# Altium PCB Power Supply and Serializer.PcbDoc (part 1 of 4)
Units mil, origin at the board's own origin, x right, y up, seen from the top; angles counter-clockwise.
Board outline 986 x 985 mil, 8 copper layers (TOP, GND1, INNER1, GND2, PWR1, INNER2, GND3, BOTTOM), stack 60.4 mil thick; 91 components, 64 nets, 288 pads, 200 vias.
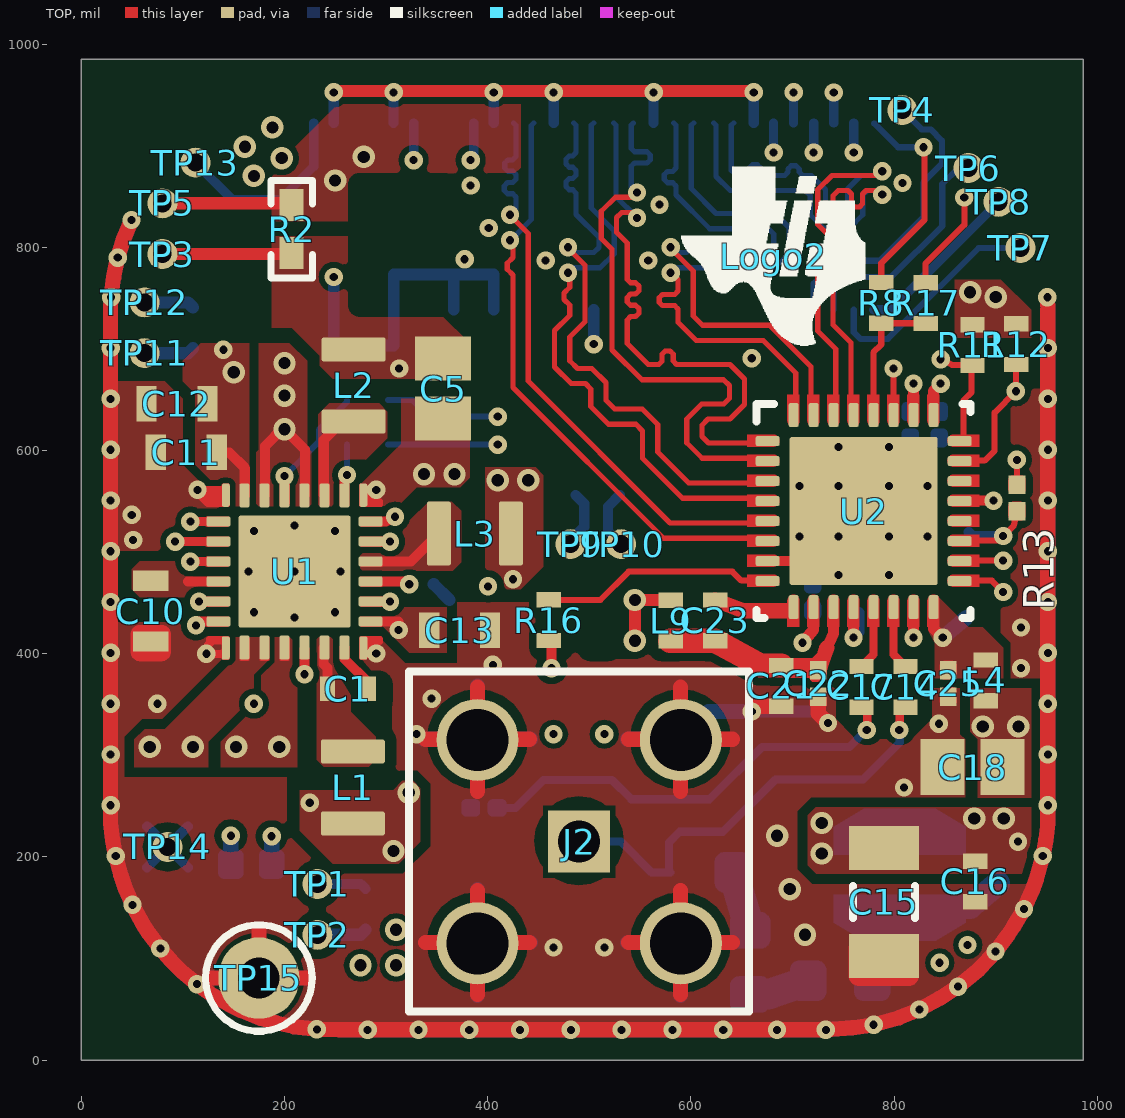
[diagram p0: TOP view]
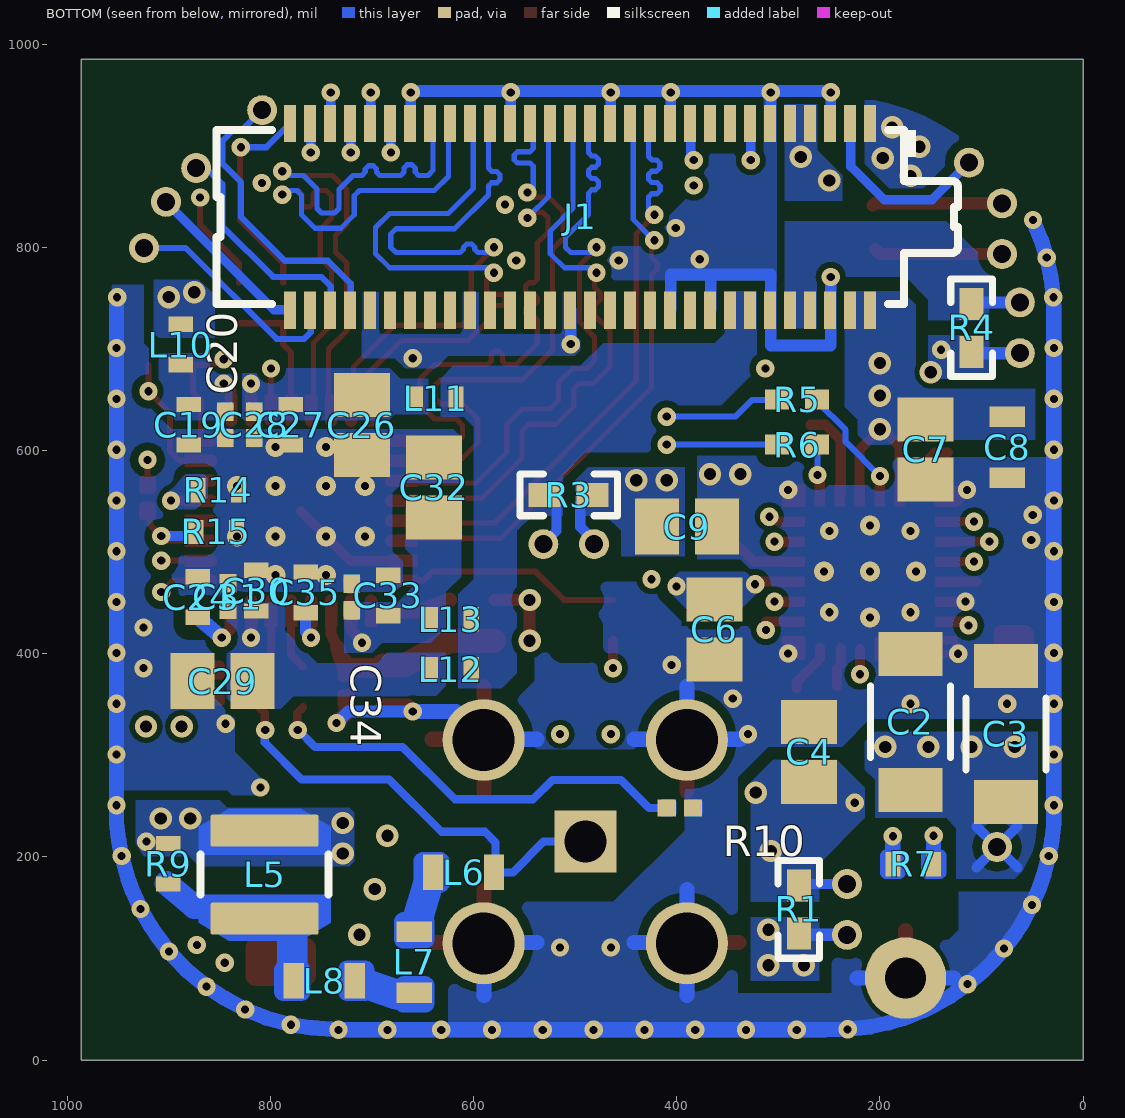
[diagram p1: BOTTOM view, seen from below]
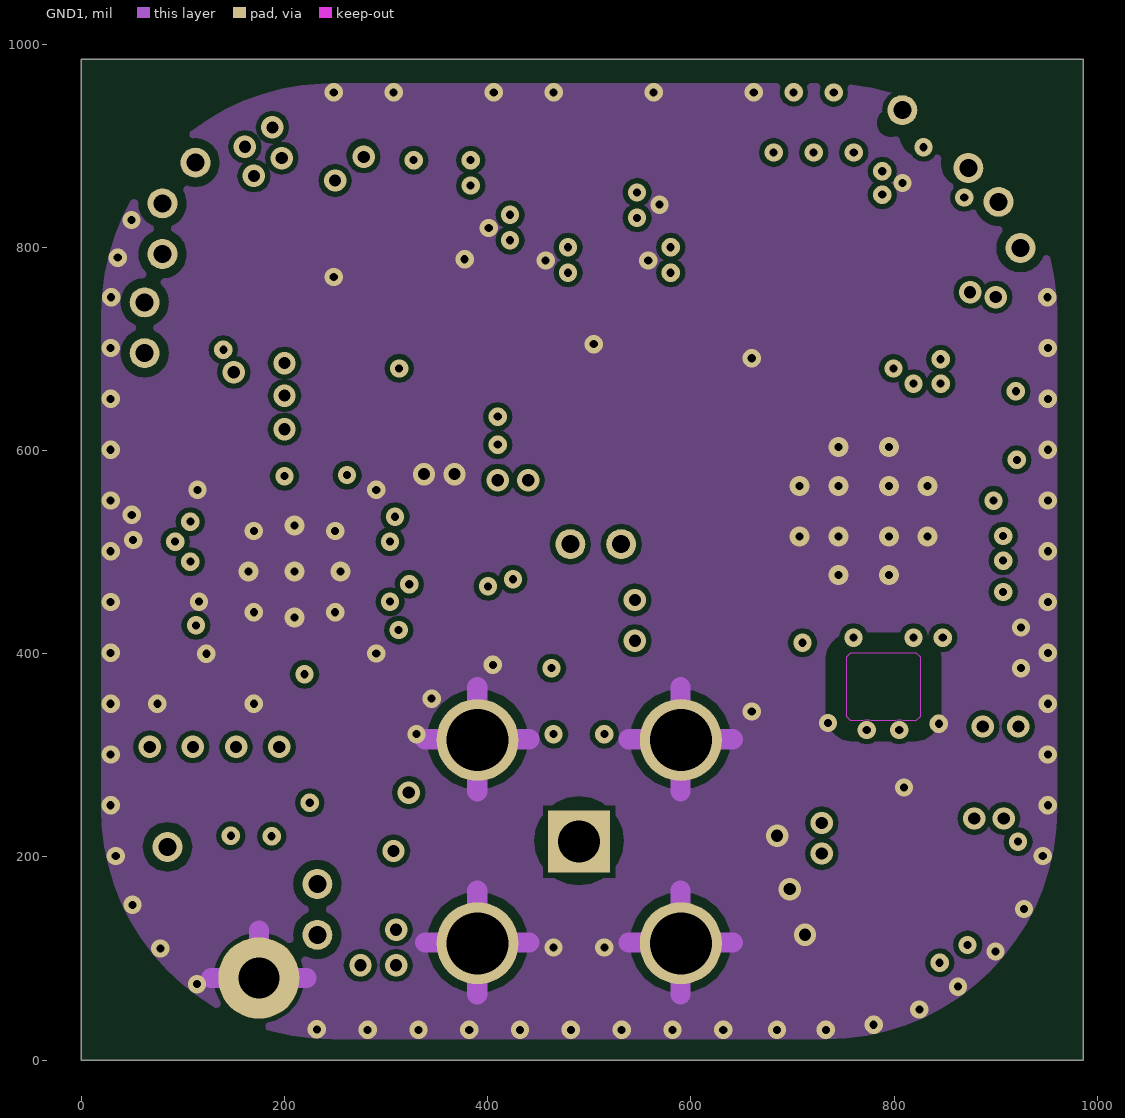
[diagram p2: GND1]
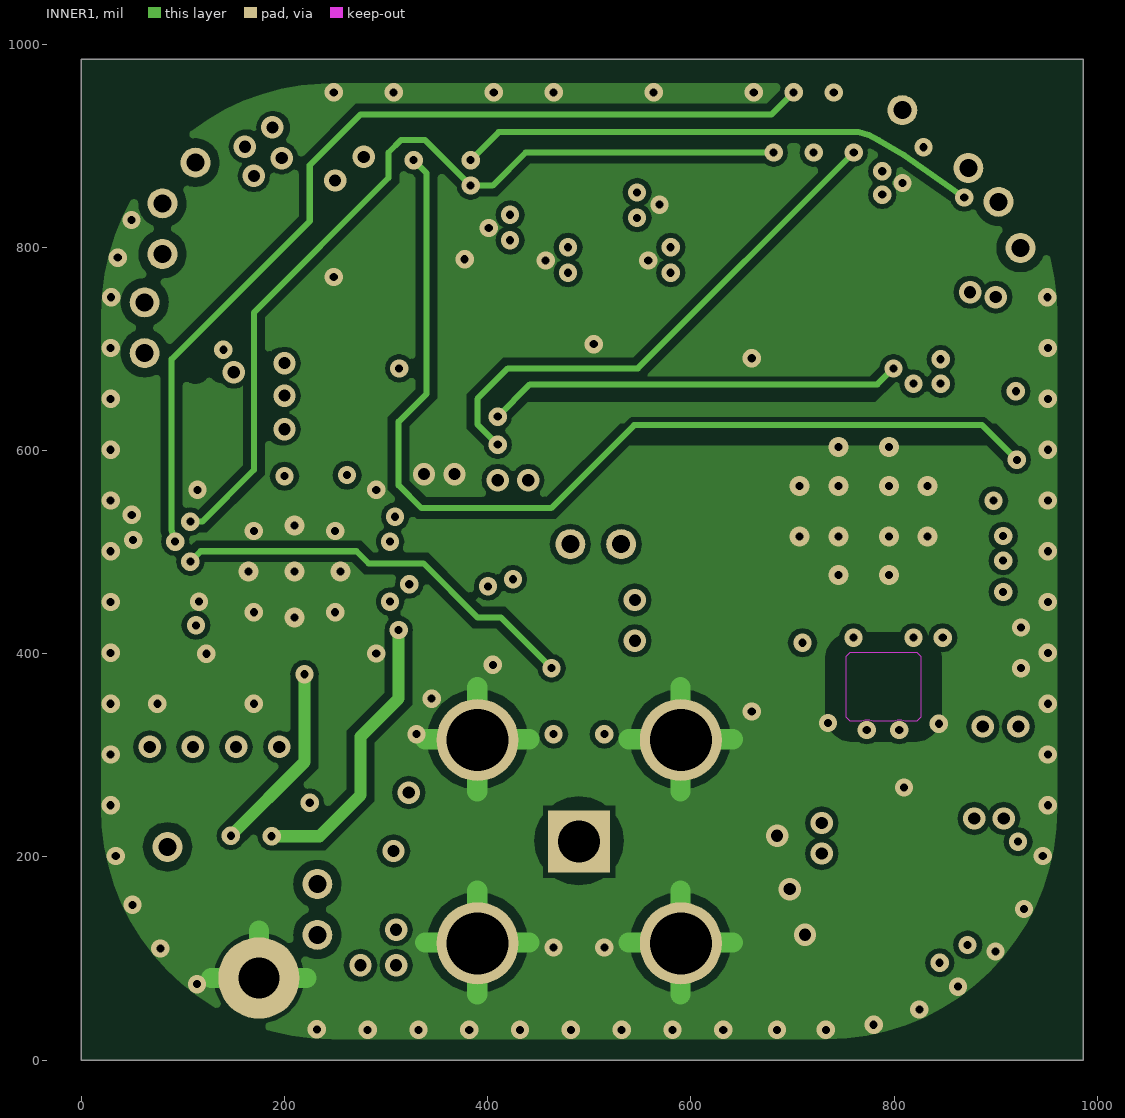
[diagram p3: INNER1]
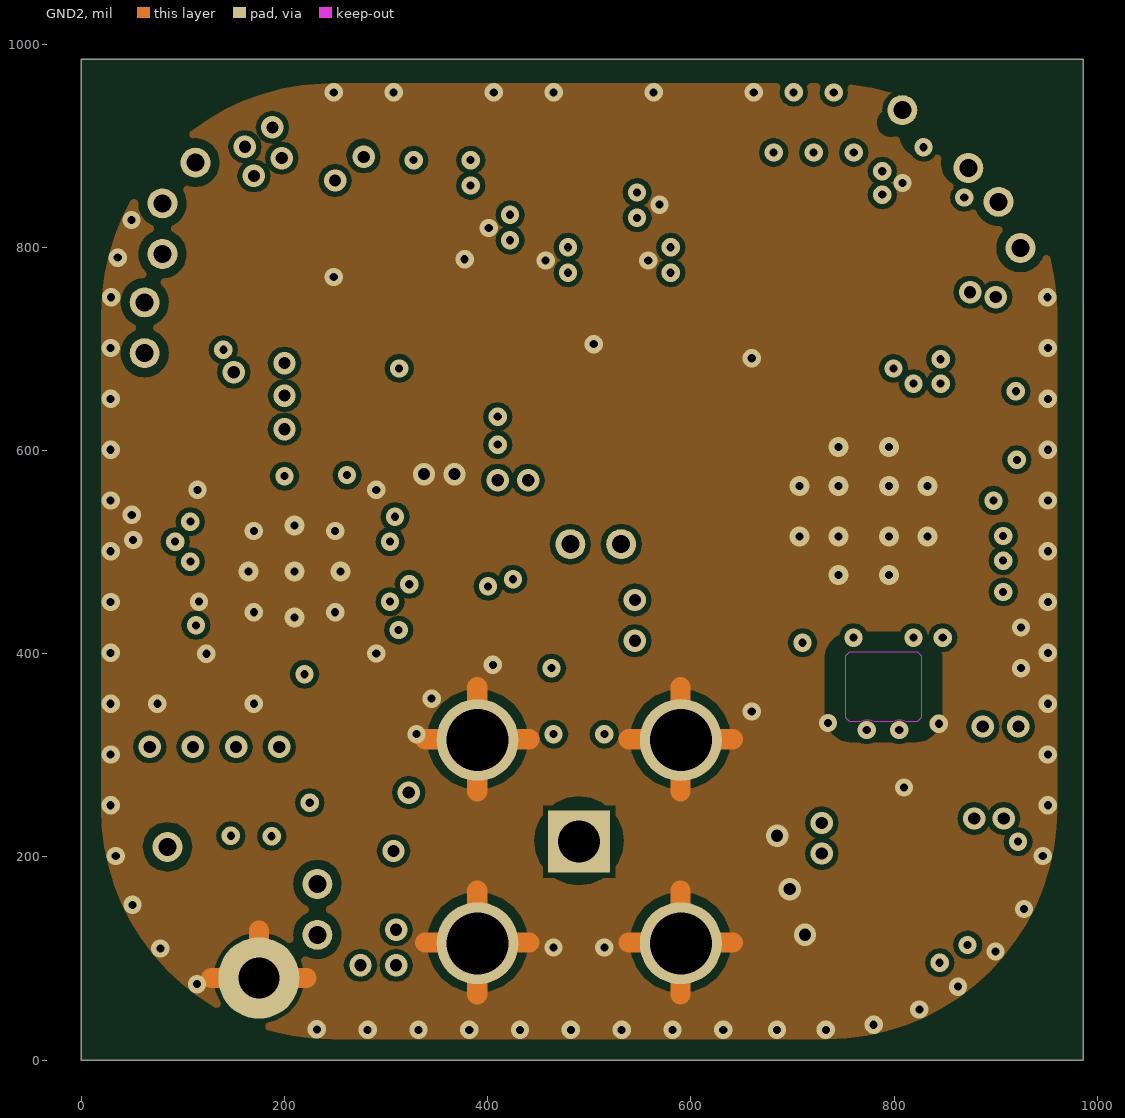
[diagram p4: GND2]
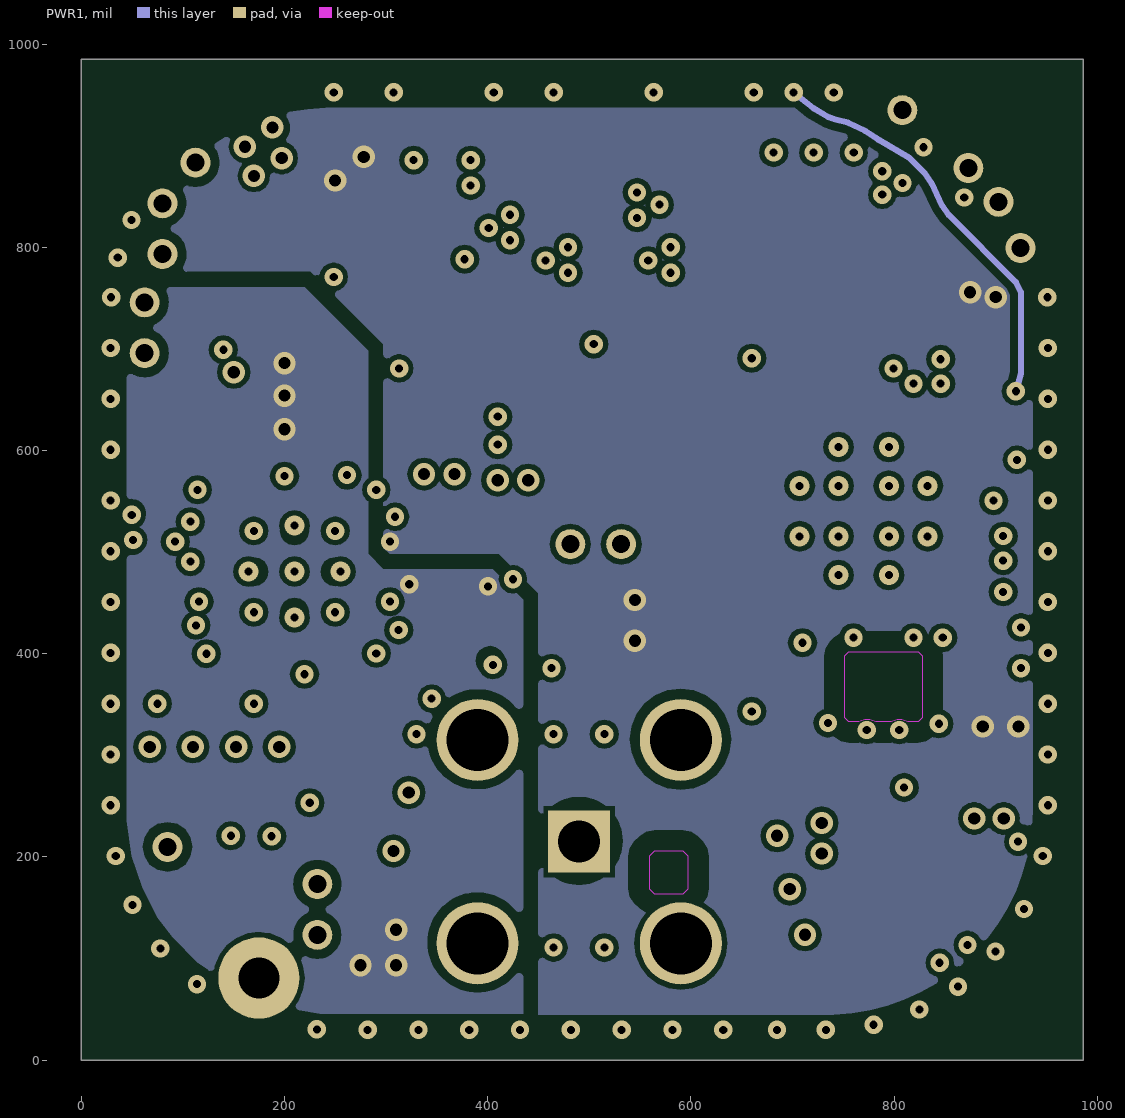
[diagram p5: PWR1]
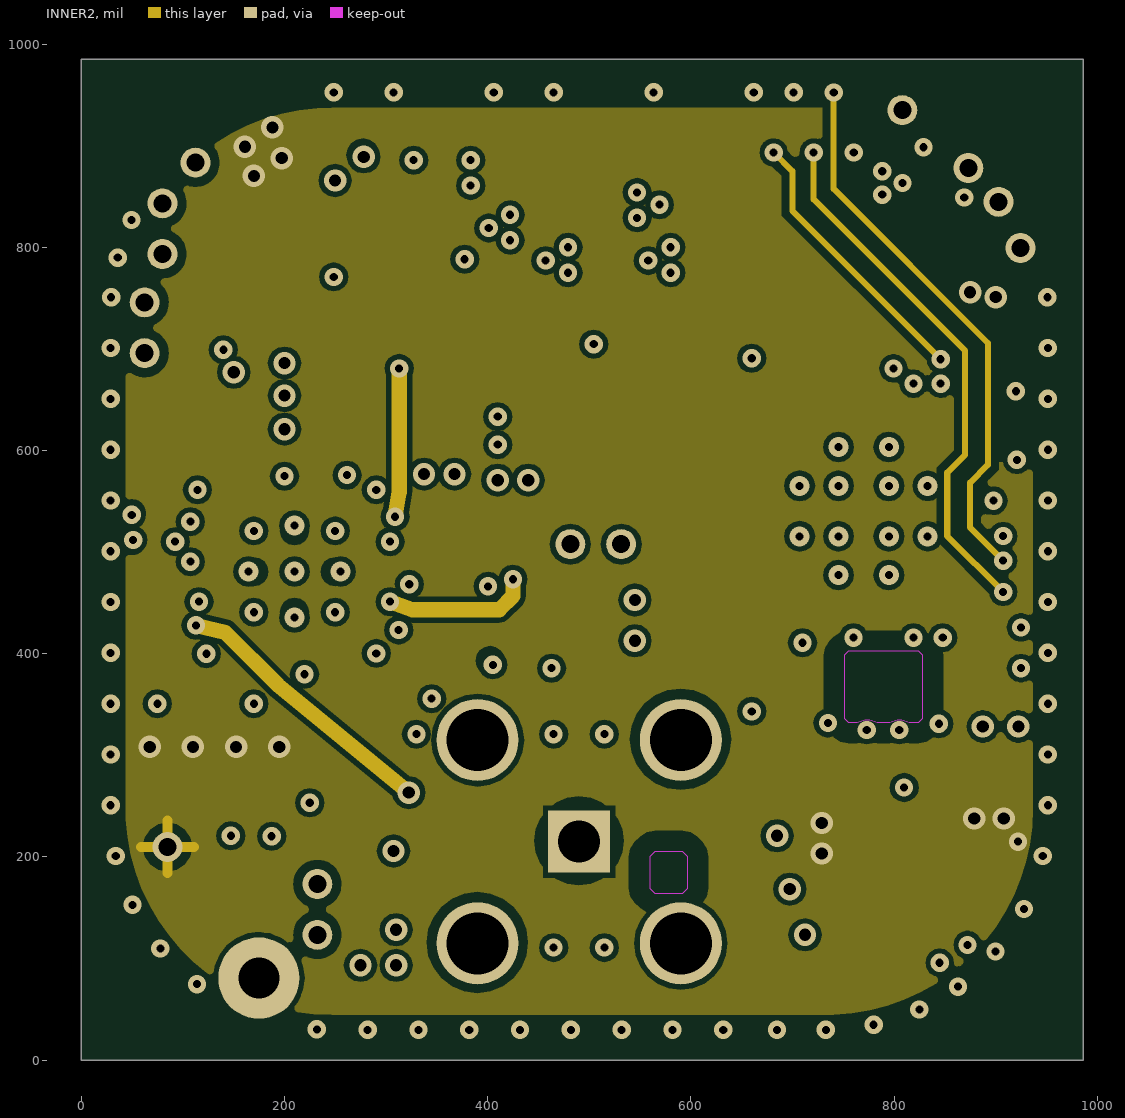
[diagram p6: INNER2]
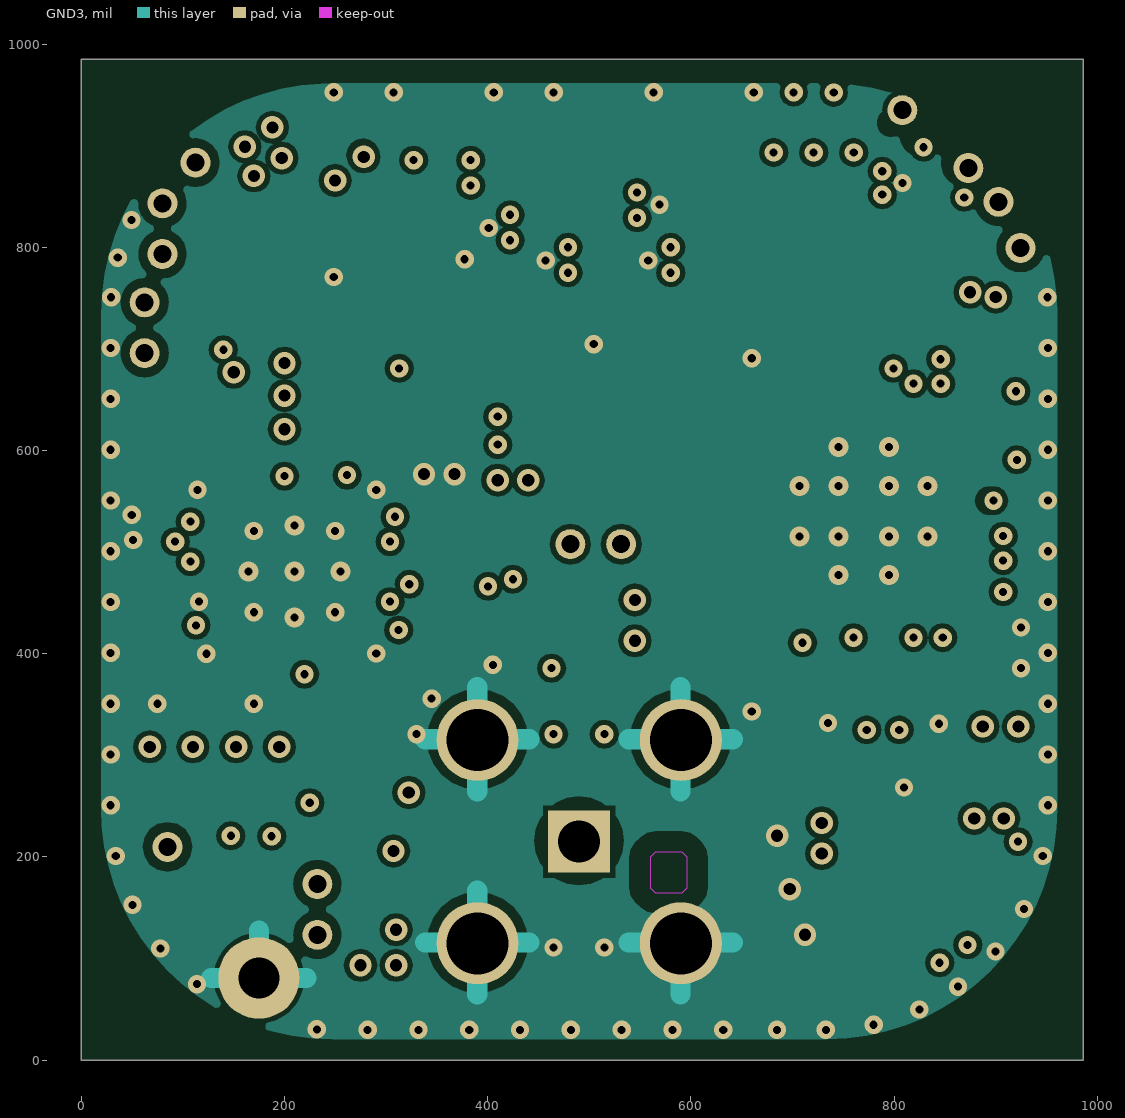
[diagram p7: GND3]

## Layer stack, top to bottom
Top Solder: solder mask 0.4, Solder Resist, Dk 3.5
TOP: signal copper 2.1
Dielectric 1: core 3.2, FR-4, Dk 3.8
GND1: signal copper 1.3
Dielectric2: core 5, FR-4, Dk 3.8
INNER1: signal copper 1.3
Dielectric3: core 9, FR-4, Dk 3.8
GND2: signal copper 1.3
Dielectric4: core 14, FR-4, Dk 3.8
PWR1: signal copper 1.3
Dielectric5: core 9, FR-4, Dk 3.8
INNER2: signal copper 1.3
Dielectric6: core 5, FR-4, Dk 3.8
GND3: signal copper 1.3
Dielectric7: core 3.2, FR-4, Dk 3.8
BOTTOM: signal copper 2.1
Bottom Solder: solder mask 0.4, Solder Resist, Dk 3.5

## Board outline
0,0 0,985 986,985 986,0

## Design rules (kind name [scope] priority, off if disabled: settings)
AcuteAngle [All] p1 off: minimum=4.50000000000000E+0001 checktracksonly=FALSE
AssemblyTestPointUsage [All] p1: valid=2
Clearance Clearance_BoardEdge_MountingHoles [OnCopper and InComponentClass('Mounting Holes') vs IsKeepOut] p1 off: gap=30 ignorepadtopadclearanceinfootprint=FALSE except(0: Arc-Hole Track-Hole SMDPad-Hole THPad-Hole Via-Hole Fill-Hole Poly-Hole Region-Hole Text-Hole)
Clearance Clearance_BoardEdge_Poly [OnCopper and InPoly vs IsKeepOut] p2: gap=20 ignorepadtopadclearanceinfootprint=FALSE except(0: Arc-Hole Track-Hole SMDPad-Hole THPad-Hole Via-Hole Fill-Hole Poly-Hole Region-Hole Text-Hole)
Clearance Clearance_BoardEdge [OnCopper and Not InComponentClass('Logo') and not InComponentClass('FiducialMark') and not InRegion(1000,500,4000,800) and Not IsKeepout vs IsKeepOut and Not OnLayer('Keep-out Layer')] p3: gap=11 ignorepadtopadclearanceinfootprint=FALSE except(0: Arc-Hole Track-Hole SMDPad-Hole THPad-Hole Via-Hole Fill-Hole Poly-Hole Region-Hole Text-Hole)
Clearance Clearance_Poly [InPolygon] p4: gap=10 ignorepadtopadclearanceinfootprint=FALSE except(0: Arc-Hole Track-Hole SMDPad-Hole THPad-Hole Via-Hole Fill-Hole Poly-Hole Region-Hole Text-Hole; 5: Arc-Fill Arc-Poly Arc-Region Track-Fill Track-Poly Track-Region SMDPad-Fill SMDPad-Poly SMDPad-Region THPad-Fill THPad-Poly THPad-Region Via-Fill Via-Poly Via-Region Fill-Fill Fill-Poly Fill-Region Poly-Poly Poly-Region Region-Region)
Clearance [All] p5: gap=5 ignorepadtopadclearanceinfootprint=FALSE except(0: Arc-Hole Track-Hole SMDPad-Hole THPad-Hole Via-Hole Fill-Hole Poly-Hole Region-Hole Text-Hole)
ComponentClearance ComponentClearance_1 [issmtcomponent] p1: gap=5 collisioncheckmode=3 verticalgap=0 showdistances=FALSE
ComponentClearance ComponentClearance_Shunt [InComponentClass('Header') vs InComponentClass('Shunt')] p2: gap=0 collisioncheckmode=3 verticalgap=0 showdistances=FALSE
ComponentClearance ComponentClearance_Logo [InComponentClass('Logo')] p3: gap=0 collisioncheckmode=3 verticalgap=0 showdistances=FALSE
ComponentClearance ComponentClearance_ScrewToNut [(HasFootprint('NY PMS 440 0025 PH')) vs (HasFootprint('Keystone_1902C'))] p4: gap=5 collisioncheckmode=3 verticalgap=10 showdistances=FALSE
ComponentClearance ComponentClearance_MountingHoles [InComponentClass('Mounting Holes')] p5: gap=50 collisioncheckmode=3 verticalgap=50 showdistances=FALSE
ComponentClearance ComponentClearance_SmallPassives [HasFootprint('0201*') or HasFootprint('0402*') or HasFootprint('0508') or HasFootprint('0603*') or HasFootprint('0612') or HasFootprint('0805*') or HasFootprint('0815*') or HasFootprint('0830*') or HasFootprint('1206*') or HasFootprint('1210*') or HasFootprint('1808*') or HasFootprint('1812*') or HasFootprint('1825*') or HasFootprint('2010*') or HasFootprint('2220*') or HasFootprint('2225*') or HasFootprint('2512*') or HasFootprint('2728*') or HasFootprint('3518*') vs HasFootprint('0201*') or HasFootprint('0402*') or HasFootprint('0508') or HasFootprint('0603*') or HasFootprint('0612') or HasFootprint('0805*') or HasFootprint('0815*') or HasFootprint('0830*') or HasFootprint('1206*') or HasFootprint('1210*') or HasFootprint('1808*') or HasFootprint('1812*') or HasFootprint('1825*') or HasFootprint('2010*') or HasFootprint('2220*') or HasFootprint('2225*') or HasFootprint('2512*') or HasFootprint('2728*') or HasFootprint('3518*')] p6: gap=5 collisioncheckmode=3 verticalgap=0 showdistances=FALSE
ComponentClearance ComponentClearance_THtoSMT [IsThruComponent vs IsSMTComponent] p7: gap=0 collisioncheckmode=3 verticalgap=0 showdistances=FALSE
ComponentClearance ComponentClearance_THtoTH [IsThruComponent vs IsThruComponent] p8: gap=0 collisioncheckmode=3 verticalgap=0 showdistances=FALSE
ComponentClearance [All] p9: gap=5 collisioncheckmode=3 verticalgap=0 showdistances=FALSE
DiffPairsRouting DiffPair_Diff100_DiffPairsRouting [InDifferentialPairClass('Diff100')] p1: maxlimit=8 minlimit=5 mostfreqgap=8 toplayer_mingap=8 toplayer_minwidth=8 toplayer_maxwidth=8 toplayer_prefwidth=8 midlayer1_mingap=8 midlayer1_minwidth=8 midlayer1_maxwidth=8 midlayer1_prefwidth=8 midlayer2_mingap=8 midlayer2_minwidth=8 midlayer2_maxwidth=8 midlayer2_prefwidth=8 midlayer3_maxgap=5 midlayer3_prefgap=5 midlayer3_minwidth=5 midlayer3_maxwidth=5 midlayer3_prefwidth=5 midlayer4_maxgap=5 midlayer4_prefgap=5 midlayer4_minwidth=5 midlayer4_maxwidth=5 midlayer4_prefwidth=5 midlayer5_mingap=8 midlayer5_minwidth=8 midlayer5_maxwidth=8 midlayer5_prefwidth=8 midlayer6_mingap=8 midlayer6_minwidth=8 midlayer6_maxwidth=8 midlayer6_prefwidth=8 bottomlayer_mingap=8 bottomlayer_minwidth=8 bottomlayer_maxwidth=8 bottomlayer_prefwidth=8 maxuncoupledlength=500
DiffPairsRouting [All] p2: maxlimit=100 minlimit=5 mostfreqgap=5 toplayer_maxgap=5 toplayer_minwidth=4 toplayer_maxwidth=15 toplayer_prefwidth=4 midlayer1_maxgap=5 midlayer1_minwidth=4 midlayer1_maxwidth=15 midlayer1_prefwidth=4 midlayer2_maxgap=5 midlayer2_minwidth=4 midlayer2_maxwidth=15 midlayer2_prefwidth=4 midlayer3_maxgap=5 midlayer3_minwidth=4 midlayer3_maxwidth=15 midlayer3_prefwidth=4 midlayer4_maxgap=5 midlayer4_minwidth=4 midlayer4_maxwidth=15 midlayer4_prefwidth=4 midlayer5_minwidth=4 midlayer5_maxwidth=15 midlayer5_prefwidth=4 midlayer6_minwidth=4 midlayer6_maxwidth=15 midlayer6_prefwidth=4 bottomlayer_maxgap=5 bottomlayer_minwidth=4 bottomlayer_maxwidth=15 bottomlayer_prefwidth=4 maxuncoupledlength=1000
FabricationTestPointUsage TestPointUsage [All] p1: valid=2 allowmultiple=FALSE
FabricationTestpoint Testpoint [All] p1: side=3 testpointundercomponent=TRUE minsize=40 maxsize=100 preferedsize=60 minholesize=0 maxholesize=40 preferedholesize=32 testpointgrid=1 allowsidetop=TRUE allowsidebottom=TRUE usegrid=TRUE gridtolerance=0.01
FanoutControl Fanout_LCC [IsLCC] p1: bgadir=Out bgaviamode=Centered fanoutstyle=Auto fanoutdirection=Alternating viagrid=1 // Fanout_LCC (Default Rule)
FanoutControl Fanout_BGA [IsBGA] p2: bgadir=Out bgaviamode=Centered fanoutstyle=Auto fanoutdirection=Alternating viagrid=1 // Fanout_BGA (Default Rule)
FanoutControl Fanout_Default [All] p4: bgadir=Out bgaviamode=Centered fanoutstyle=Auto fanoutdirection=Alternating viagrid=1 // Fanout_Default (Default Rule)
FanoutControl Fanout_Small [(CompPinCount < 5)] p5: bgadir=Out bgaviamode=Centered fanoutstyle=Auto fanoutdirection=OutThenIn viagrid=1 // Fanout_Small (Default Rule)
HoleSize [All] p1: absolutevalues=TRUE maxlimit=280 minlimit=6 maxpercent=80.000 minpercent=20.000
MatchedLengths DiffPair_Diff100_MatchedLengths [InDifferentialPairClass('Diff100')] p1: tolerance=25 checknetsindiffpair=FALSE checkdiffpairvsdiffpair=TRUE checkxsignals=TRUE checkothers=TRUE
MinimumAnnularRing MinimumAnnularRing_ThermalPadVias [IsVia and InAnyComponent] p1: minimumring=5.91
MinimumAnnularRing [All] p2: minimumring=2
MinimumSolderMaskSliver MinimumSolderMaskSliver_Logo [InComponentClass('Logo') vs InComponentClass('Logo')] p1: minsoldermaskwidth=0.7
MinimumSolderMaskSliver [All] p2: minsoldermaskwidth=1
PlaneConnect [All] p1: planeconnectstyle=Relief reliefexpansion=10 reliefentries=4 reliefconductorwidth=10 reliefairgap=10
PolygonConnect [All] p1: connectstyle=Direct reliefconductorwidth=10 reliefentries=4 polygonreliefangle="90 Angle" airgapwidth=10
RoutingVias ThermalPadVias [IsVia and InAnyComponent] p1: holewidth=7.87 width=19.68 viastyle="Through Hole" minholewidth=7.87 minwidth=19.68 maxholewidth=12.99 maxwidth=23.62
RoutingVias [All] p2: holewidth=10 width=22 viastyle="Through Hole" minholewidth=6 minwidth=10 maxholewidth=40 maxwidth=65
SMDToCorner [All] p1: distance=25000
SilkToBoardRegionClearance [Not ((IsComment or IsDesignator) And (Hide <> 'False')) and not InRegion(1000,500,4000,800)] p1:
SilkToSilkClearance [All] p1: silktosilkclearance=0
SilkToSolderMaskClearance SilkscreenOverComponentPads [IsPad] p1: minsilkscreentomaskgap=0.2 clearancetoexposedcopper=TRUE
SolderMaskExpansion [All] p1: expansion=1
Width [All] p1: maxlimit=100 minlimit=5 preferedwidth=10 midlayer5_minwidth=6 midlayer6_minwidth=6 minimp=50.000000 maximp=50.000000 favimp=50.000000 checkconnectedcopper=TRUE
15 further rules are at their usual default settings.

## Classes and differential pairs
component class "Power Supply and Serializer": C1 C2 C3 C4 C5 C6 C7 C8 C9 C10 C11 C12 C13 C14 C15 C16 C17 C18 C19 C20 C21 C22 C23 C24 C25 C26 C27 C28 C29 C30 C31 C32 C33 C34 C35 J1 J2 L1 L2 L3 L4 L5 L6 L7 L8 L9 L10 L11 L12 L13 R1 R2 R3 R4 R5 R6 R7 R8 R9 R10 R11 R12 R13 R14 R15 R16 R17 TP1 TP2 TP3 TP4 TP5 TP6 TP7 TP8 TP9 TP10 TP11 TP12 TP13 TP14 TP15 U1 U2
component class Logo: Logo2
component class D3-Ref-Design_Hardware: FID1 FID2 FID3 Logo2 ZZ1 ZZ2 ZZ3
component class FiducialMark: FID1 FID2 FID3
component class AssemblyNote: ZZ1 ZZ2 ZZ3
differential pair CSI2_D3: +CSI2_D3_P -CSI2_D3_N
differential pair CSI2_D2: +CSI2_D2_P -CSI2_D2_N
differential pair CSI2_D1: +CSI2_D1_P -CSI2_D1_N
differential pair CSI2_D0: +CSI2_D0_P -CSI2_D0_N
differential pair CSI2_CK: +CSI2_CK_P -CSI2_CK_N

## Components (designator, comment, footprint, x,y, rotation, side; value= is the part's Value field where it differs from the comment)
C1 "CGA2B3X7R1H104K050BB" 0402S 262.3,365.59 r0 top value=0.1uF
C2 "CGA5L1X7R1E106K160AE" 1206_190 170,333 r90 bottom value=10uF
C3 "CGA5L1X7R1E106K160AE" 1206_190 76,321 r90 bottom value=10uF
C4 "C0805C106J8RACAUTO" 0805L 269.8,303.3 r90 bottom value=10uF
C5 "C0805C106J8RACAUTO" 0805L 356,661 r270 top value=10uF
C6 "C0805C106J8RACAUTO" 0805L 363,424 r270 bottom value=10uF
C7 "C0805C106J8RACAUTO" 0805L 155,601 r270 bottom value=10uF
C8 "CGA3E1X7R1E105K080AC" 0603S 74.8,603.3 r270 bottom value=1uF
C9 "C0805C106J8RACAUTO" 0805L 390,525 r180 bottom value=10uF
C10 "CGA3E1X7R1E105K080AC" 0603S 68.3,441.96 r270 top value=1uF
C11 "CGA3E1X7R1E105K080AC" 0603S 103.12,598.09 r180 top value=1uF
C12 "CGA3E1X7R1E105K080AC" 0603S 94.14,645.9 r180 top value=1uF
C13 "CGA3E1X7R1E105K080AC" 0603S 372.3,423.3 r0 top value=1uF
C14 "CGA2B3X7R1H333K050BB" 0402S 811.14,367.32 r270 top value=0.033uF
C15 "C3216X5R1E226M160AB" 1206_190L 789.8,155.8 r270 top value=22uF
C16 "CGA2B3X7R1H104K050BB" 0402S 879.8,175.8 r270 top value=0.1uF
C17 "CGA2B3X7R1H153K050BB" 0402S 767.83,367.32 r270 top value=0.015uF
C18 "GCM21BR70J106KE22L" 0805L 877.3,288.3 r0 top value=10uF
C19 "CGA2B3X7R1H104K050BB" 0402S 880.3,625.3 r270 bottom value=0.1uF
C20 "CGA1A2X7R1A103K030BA" 0201_033 844.3,625.3 r270 bottom value=0.01uF
C21 "CGA2B3X7R1H104K050BB" 0402S 688.8,368.3 r270 top value=0.1uF
C22 "CGA1A2X7R1A103K030BA" 0201_033 725.27,370.75 r270 top value=0.01uF
C23 "GCM155R71H223KA55D" 0402S 623.8,432.79 r90 top value=0.022uF
C24 "CGA2B3X7R1H104K050BB" 0402S 871.3,455.8 r90 bottom value=0.1uF
C25 "CGA1A2X7R1A103K030BA" 0201_033 853.3,370.8 r270 top value=0.01uF
C26 "GCM21BR70J106KE22L" 0805L 710,625 r270 bottom value=10uF
C27 "CGA2B3X7R1H104K050BB" 0402S 779.8,625.3 r270 bottom value=0.1uF
C28 "CGA1A2X7R1A103K030BA" 0201_033 815.8,625.3 r270 bottom value=0.01uF
C29 "GCM21BR70J106KE22L" 0805L 847,373 r0 bottom value=10uF
C30 "CGA2B3X7R1H104K050BB" 0402S 813.89,462.06 r90 bottom value=0.1uF
C31 "CGA1A2X7R1A103K030BA" 0201_033 841.73,456.17 r90 bottom value=0.01uF
C32 "GCM21BR70J106KE22L" 0805L 638.8,563.8 r90 bottom value=10uF
C33 "CGA2B3X7R1H104K050BB" 0402S 683.8,457.3 r90 bottom value=0.1uF
C34 "CGA1A2X7R1A103K030BA" 0201_033 719.8,455.8 r90 bottom value=0.01uF
C35 "CGA2B3X7R1H104K050BB" 0402S 765.22,460.38 r90 bottom value=0.1uF
FID1 "Fiducial" Fiducial10-20 4330.71,669.29 r0 top
FID2 "Fiducial" Fiducial10-20 4320.87,482.28 r0 top
FID3 "Fiducial" Fiducial10-20 4320,300 r0 top
J1 "SS5-30-3.50-L-D-K-TR" Samtec_SS5-30-3_50-x-D-K 495,830 r270 bottom
J2 "59S10H-40ML5-Z" Rosenberger_59S10H-40ML5-Z 490,215 r0 top
L1 "TFM201610ALMA1R5MTAA" TFM201610ALMA 267.2,268.3 r270 top value=1.5uH
L2 "TFM201610ALMA1R0MTAA" TFM201610ALMA 268,664 r90 top value=1uH
L3 "TFM201610ALMA1R0MTAA" TFM201610ALMA 387.3,518.3 r0 top value=1uH
L4 "BLM15AG102SN1D" 0402S 890,373.68 r90 top value="1000 ohm"
L5 "LQH3NPZ100MJRL" LQH3NPZ_JR 805.7,182.5 r90 bottom value=10uH
L6 "BLM18HE152SN1D" 0603S 609.8,184.8 r0 bottom value="1500 ohm"
L7 "BLM18HE152SN1D" 0603S 658.3,96.2 r270 bottom value="1500 ohm"
L8 "BLM18HE152SN1D" 0603S 746.9,78.1 r0 bottom value="1500 ohm"
L9 "BLM15AG102SN1D" 0402S 580.21,432.6 r270 top value="1000 ohm"
L10 "BLM15AG102SN1D" 0402S 888.3,704.3 r270 bottom value="1000 ohm"
L11 "BLM15AG102SN1D" 0402S 637.32,650.82 r0 bottom value="1000 ohm"
L12 "BLM15AG102SN1D" 0402S 622.3,384.8 r0 bottom value="1000 ohm"
L13 "BLM15AG102SN1D" 0402S 622.3,433.76 r0 bottom value="1000 ohm"
Logo2 "Texas Instruments" TI_Symbol_Overlay_Small 681,791 r0 top
R1 "ERJ-2GE0R00X" 0402 279.8,148.3 r270 bottom value=0
R2 "ERJ-2GE0R00X" 0402 207.06,817.8 r90 top value=0
R3 "ERJ-2GE0R00X" 0402 506.3,556.3 r0 bottom value=0
R4 "ERJ-2GE0R00X" 0402 109.8,720.8 r270 bottom value=0
R5 "ERJ-2GE0R00X" 0402L 281.49,650.18 r180 bottom value=0
R6 "ERJ-2GE0R00X" 0402L 281.6,605.8 r180 bottom value=0
R7 "CRCW04024K70JNED" 0402S 167.22,192.8 r180 bottom value=4.7k
R8 "ERJ-2GE0R00X" 0402S 787.3,745.3 r90 top value=0
R9 "CRCW04024K02FKED" 0402S 900.42,193.3 r90 bottom value=4.02k
R10 "CRCW020149R9FKED" 0201 397,248 r0 bottom value=49.9
R11 "CRCW04024K70JNED" 0402S 877.09,703.79 r90 top value=4.7k
R12 "CRCW04024K70JNED" 0402S 920.24,704.7 r90 top value=4.7k
R13 "ERJ-1GNJ220C" 0201 920.8,553.3 r270 top value=22
R14 "CRCW0402402RFKED" 0402S 851.3,560.7 r0 bottom value=402
R15 "CRCW0402402RFKED" 0402S 853.3,519.8 r0 bottom value=402
R16 "ERJ-2GE0R00X" 0402S 460,433 r90 top value=0
R17 "ERJ-2GE0R00X" 0402S 831,745 r90 top value=0
TP1 "TP_H0.45P0.75" TP_H045P075 232.3,173.3 r90 top
TP2 "TP_H0.45P0.75" TP_H045P075 232.3,123.3 r90 top
TP3 "TP_H0.45P0.75" TP_H045P075 79.8,793.3 r0 top
TP4 "TP_H0.45P0.75" TP_H045P075 808,935 r0 top
TP5 "TP_H0.45P0.75" TP_H045P075 79.8,843.3 r0 top
TP6 "TP_H0.45P0.75" TP_H045P075 873,878 r0 top
TP7 "TP_H0.45P0.75" TP_H045P075 924.3,799.3 r0 top
TP8 "TP_H0.45P0.75" TP_H045P075 902.8,844.8 r0 top
TP9 "TP_H0.45P0.75" TP_H045P075 481.3,507.8 r0 top
TP10 "TP_H0.45P0.75" TP_H045P075 531.3,507.8 r0 top
TP11 "TP_H0.45P0.75" TP_H045P075 62.3,695.8 r0 top
TP12 "TP_H0.45P0.75" TP_H045P075 62.3,745.8 r0 top
TP13 "TP_H0.45P0.75" TP_H045P075 112.3,883.3 r0 top
TP14 "TP_H0.45P0.75" TP_H045P075 84.8,209.8 r0 top
TP15 "5001" Keystone5001 174.8,80.8 r0 top
U1 "TPS650330QRGEQ1" RGE0024K 209.86,480.86 r0 top
U2 "DS90UB953TRHBRQ1" RHB0032P 770,540.39 r0 top
ZZ1 "These assemblies are ESD sensitive, ESD precautions shall be observed." AssemblyNote 174.75,1528.11 r0 top
ZZ2 "These assemblies must be clean and free from flux and all contaminants. Use of no clean flux is not acceptable." AssemblyNote 174.75,1439.56 r0 top
ZZ3 "These assemblies must comply with workmanship standards IPC-A-610 Class 2, unless otherwise specified." AssemblyNote 174.75,1351 r0 top

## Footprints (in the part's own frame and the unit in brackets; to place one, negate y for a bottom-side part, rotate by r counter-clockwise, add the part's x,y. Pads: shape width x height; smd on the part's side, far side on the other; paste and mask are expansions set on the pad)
0201 [mm] "Data from Kemet datasheet CC101_COM dated 7/28/11"
  rect 0.46x0.42 smd mask+0.048: 1(-0.33,0) 2(0.33,0)
  body extent -0.31,-0.16 0.31,0.16, height 0.26
0201_033 [mm] "SMD, 2-Leads, Height 0.33mm"
  rect 0.46x0.42 smd mask+0.048: 1(-0.33,0) 2(0.33,0)
  body extent -0.31,-0.16 0.31,0.16, height 0.33
0402 [mm] "0402 from SM-752 data"
  rect 0.8x0.6 smd: 1(-0.6,0) 2(0.6,0)
  silkscreen extent -1.22,-0.52 1.22,0.52, body extent -0.55,-0.3 0.55,0.3, height 0.6
0402L [mm] "0402 from SM-752 data"
  rect 0.6x0.5 smd: 1(-0.5,0) 2(0.5,0)
  body extent -0.55,-0.3 0.55,0.3, height 0.6
0402S [mil] "Based on C0402S footprint from PADS legacy"
  rect 15x24 smd: 1(-20,0) 2(20,0)
  body extent -22,-12 22,12, height 24
0603S [mil]
  rect 20x35 smd: 1(-30,0) 2(30,0)
  body extent -34,-19 34,19, height 39
0805L [mm] "0805 from SM-752 data"
  rect 1.1x1.4 smd: 1(-0.75,0) 2(0.75,0)
  body extent -1.1,-0.72 1.1,0.72, height 1.45
1206_190 [mm] "1206_190"
  rect 1.1x1.6 smd: 1(-1.7,0) 2(1.7,0)
  silkscreen extent -0.9,-1 0.9,1, body extent -1.75,-0.95 1.75,0.95, height 1.9
1206_190L [mm] "1206_190"
  rect 1.1x1.75 smd: 1(-1.35,0) 2(1.35,0)
  silkscreen extent -0.4,-0.77 0.4,0.77, body extent -1.75,-0.95 1.75,0.95, height 1.9
AssemblyNote [mil] "Assembly Note"
Fiducial10-20 [mm]
  round 1 smd mask+0.5: 1(0,0)
  TOP keep-out circle w1.178: c0,0 r0.5
Keystone5001 [mil] "For Keystone 500x miniature loop terminals"
  round 80 hole 40: 1(0,0)
  silkscreen extent -52,-52 52,52, body extent -49,-49 49,49, height 182
LQH3NPZ_JR [mm] "SMD, 2-Leads, Body 3x3mm"
  rrect12% 0.8x2.7 smd: 1(-1.1,0) 2(1.1,0)
  silkscreen extent -0.5,-1.6 0.5,1.6, body extent -1.6,-1.6 1.6,1.6, height 1.2
RGE0024K [mm] "VQFN, 24-Leads, Body 4x4mm, Pitch 0.5mm"
  rrect40% 0.6x0.25 smd: 1(-1.9,1.25) 2(-1.9,0.75) 3(-1.9,0.25) 4(-1.9,-0.25) 5(-1.9,-0.75) 6(-1.9,-1.25) 13(1.9,-1.25) 14(1.9,-0.75) 15(1.9,-0.25) 16(1.9,0.25) 17(1.9,0.75) 18(1.9,1.25)
  rrect40% 0.25x0.6 smd: 7(-1.25,-1.9) 8(-0.75,-1.9) 9(-0.25,-1.9) 10(0.25,-1.9) 11(0.75,-1.9) 12(1.25,-1.9) 19(1.25,1.9) 20(0.75,1.9) 21(0.25,1.9) 22(-0.25,1.9) 23(-0.75,1.9) 24(-1.25,1.9)
  rrect4% 2.8x2.8 smd paste-4: 25(0,0)
  rrect50% 0.2x0.58 smd: A1(-1.72,1.91) A2(-1.72,-1.91) A3(1.72,-1.91) A4(1.72,1.91)
  rrect8% 1.23x1.23 on Top Paste: ""(-0.715,-0.715) ""(-0.715,0.715) ""(0.715,-0.715) ""(0.715,0.715)
  TOP region: -2.2,1.67 -2.2,1.77 -2.196,1.789 -2.185,1.805 -2.169,1.816 -2.15,1.82 -2.15,1.82 -1.67,1.82 -1.651,1.816 -1.635,1.805 -1.624,1.789 -1.62,1.77 -1.62,1.77 -1.62,1.67 -1.624,1.651 -1.635,1.635 -1.651,1.624 -1.67,1.62 -1.67,1.62 -2.15,1.62 -2.169,1.624 -2.185,1.635 -2.196,1.651 -2.2,1.67
  TOP region: 2.2,1.67 2.2,1.77 2.196,1.789 2.185,1.805 2.169,1.816 2.15,1.82 2.15,1.82 1.67,1.82 1.651,1.816 1.635,1.805 1.624,1.789 1.62,1.77 1.62,1.77 1.62,1.67 1.624,1.651 1.635,1.635 1.651,1.624 1.67,1.62 1.67,1.62 2.15,1.62 2.169,1.624 2.185,1.635 2.196,1.651 2.2,1.67
  TOP region: -2.2,-1.67 -2.2,-1.77 -2.196,-1.789 -2.185,-1.805 -2.169,-1.816 -2.15,-1.82 -2.15,-1.82 -1.67,-1.82 -1.651,-1.816 -1.635,-1.805 -1.624,-1.789 -1.62,-1.77 -1.62,-1.77 -1.62,-1.67 -1.624,-1.651 -1.635,-1.635 -1.651,-1.624 -1.67,-1.62 -1.67,-1.62 -2.15,-1.62 -2.169,-1.624 -2.185,-1.635 -2.196,-1.651 -2.2,-1.67
  TOP region: 2.2,-1.67 2.2,-1.77 2.196,-1.789 2.185,-1.805 2.169,-1.816 2.15,-1.82 2.15,-1.82 1.67,-1.82 1.651,-1.816 1.635,-1.805 1.624,-1.789 1.62,-1.77 1.62,-1.77 1.62,-1.67 1.624,-1.651 1.635,-1.635 1.651,-1.624 1.67,-1.62 1.67,-1.62 2.15,-1.62 2.169,-1.624 2.185,-1.635 2.196,-1.651 2.2,-1.67
  body extent -2,-2 2,2, height 1
RHB0032P [mm] "QFN, 32-Leads, Body 5x5mm, Pitch 0.5mm, Thermal Pad 3.7x3.7mm"
  rrect40% 0.6x0.25 smd: 1(-2.4,1.75) 2(-2.4,1.25) 3(-2.4,0.75) 4(-2.4,0.25) 5(-2.4,-0.25) 6(-2.4,-0.75) 7(-2.4,-1.25) 8(-2.4,-1.75) 17(2.4,-1.75) 18(2.4,-1.25) 19(2.4,-0.75) 20(2.4,-0.25) 21(2.4,0.25) 22(2.4,0.75) 23(2.4,1.25) 24(2.4,1.75)
  rrect40% 0.25x0.6 smd: 9(-1.75,-2.4) 10(-1.25,-2.4) 11(-0.75,-2.4) 12(-0.25,-2.4) 13(0.25,-2.4) 14(0.75,-2.4) 15(1.25,-2.4) 16(1.75,-2.4) 25(1.75,2.4) 26(1.25,2.4) 27(0.75,2.4) 28(0.25,2.4) 29(-0.25,2.4) 30(-0.75,2.4) 31(-1.25,2.4) 32(-1.75,2.4)
  rrect9% 1.06x1.06 on Top Paste: 33(-1.26,-1.26) 33(-1.26,0) 33(-1.26,1.26) 33(0,-1.26) 33(0,0) 33(0,1.26) 33(1.26,-1.26) 33(1.26,0) 33(1.26,1.26)
  rrect3% 3.7x3.7 smd paste-1.85: 33(0,0)
  silkscreen extent -2.67,-2.68 2.67,2.68, body extent -2.5,-2.5 2.5,2.5, height 1
Rosenberger_59S10H-40ML5-Z [mm] "Connector, HF, TH"
  rect 1.55x1.55 hole 1.05: 1(0,0)
  round 2.05 hole 1.55: 2(-2.54,2.54) 3(2.54,2.54) 4(2.54,-2.54) 5(-2.54,-2.54)
  silkscreen extent -4.25,-4.25 4.25,4.25, body extent -4.25,-5.75 4.25,4.25, height 12.45
Samtec_SS5-30-3_50-x-D-K [mm] "Receptacle, 0.5mm, 30x2, SMT"
  rect 0.93x0.3 smd: 1(-2.335,7.25) 2(2.335,7.25) 3(-2.335,6.75) 4(2.335,6.75) 5(-2.335,6.25) 6(2.335,6.25) 7(-2.335,5.75) 8(2.335,5.75) 9(-2.335,5.25) 10(2.335,5.25) 11(-2.335,4.75) 12(2.335,4.75) 13(-2.335,4.25) 14(2.335,4.25) 15(-2.335,3.75) 16(2.335,3.75) 17(-2.335,3.25) 18(2.335,3.25) 19(-2.335,2.75) 20(2.335,2.75) 21(-2.335,2.25) 22(2.335,2.25) 23(-2.335,1.75) 24(2.335,1.75) 25(-2.335,1.25) 26(2.335,1.25) 27(-2.335,0.75) 28(2.335,0.75) 29(-2.335,0.25) 30(2.335,0.25) 31(-2.335,-0.25) 32(2.335,-0.25) 33(-2.335,-0.75) 34(2.335,-0.75) 35(-2.335,-1.25) 36(2.335,-1.25) 37(-2.335,-1.75) 38(2.335,-1.75) 39(-2.335,-2.25) 40(2.335,-2.25) 41(-2.335,-2.75) 42(2.335,-2.75) 43(-2.335,-3.25) 44(2.335,-3.25) 45(-2.335,-3.75) 46(2.335,-3.75) 47(-2.335,-4.25) 48(2.335,-4.25) 49(-2.335,-4.75) 50(2.335,-4.75) 51(-2.335,-5.25) 52(2.335,-5.25) 53(-2.335,-5.75) 54(2.335,-5.75) 55(-2.335,-6.25) 56(2.335,-6.25) 57(-2.335,-6.75) 58(2.335,-6.75) 59(-2.335,-7.25) 60(2.335,-7.25)
  silkscreen extent -2.18,-9.1 2.17,9.44, body extent -2.5,-9.06 2.5,9.48, height 4
TFM201610ALMA [mm] "TDK"
  rrect17% 0.6x1.6 smd: 1(-0.9,0) 2(0.9,0)
  body extent -1.1,-0.9 1.1,0.9, height 1
TI_Symbol_Overlay_Small [mil]
  silkscreen extent -90,-88 91,88
TP_H045P075 [mm] "TP_H0.45P0.75"
  round 0.75 hole 0.45: 1(0,0)

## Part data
C1 C16 C19 C21 C24 C27 C30 C33 C35: library part CMP-0006325-2, "CAP, CERM, 0.1 uF, 50 V, +/- 10%, X7R, AEC-Q200 Grade 1, 0402", Cap_Case=0402, Manufacturer=TDK, Supplier Part Number 1=445-6899-1-ND, TempCo=X7R, Tolerance_%=10%, Value1="0.039064 ohm", Value2=50V, ValueDisplayed=0.1uF
C2 C3: library part CMP-0085253-1, "CAP, CERM, 10 µF, 25 V,+/- 10%, X7R, AEC-Q200 Grade 1, 1206", Cap_Case=1206, Manufacturer=TDK, TempCo=X7R, Tolerance_%=10%, Value2=25V, ValueDisplayed=10µF
C4 C5 C6 C7 C9: library part CMP-0081061-1, "CAP, CERM, 10 µF, 10 V,+/- 5%, X7R, AEC-Q200 Grade 1, 0805", Cap_Case=0805, Manufacturer=Kemet, Supplier Part Number 1=399-15693-1-ND, TempCo=X7R, Tolerance_%=5%, Value2=10V, ValueDisplayed=10µF
C8 C10 C11 C12 C13: library part CMP-0076705-3, "CAP, CERM, 1 µF, 25 V,+/- 10%, X7R, AEC-Q200 Grade 1, 0603", Cap_Case=1.6x0.8x0.8mm, Manufacturer=TDK, Supplier Part Number 1=445-6931-1-ND, TempCo=X7R, Tolerance_%=10%, Value2=25V, ValueDisplayed=1µF
C14: library part CMP-0006329-2, "CAP, CERM, 0.033 uF, 50 V, +/- 10%, X7R, AEC-Q200 Grade 1, 0402", Cap_Case=0402, Manufacturer=TDK, Supplier Part Number 1=445-6896-1-ND, TempCo=X7R, Tolerance_%=10%, Value1="0.098477 ohm", Value2=50V, ValueDisplayed=0.033uF
C15: library part CMP-0008654-2, "CAP, CERM, 22 uF, 25 V, +/- 20%, X5R, 1206_190", Cap_Case=1206, Manufacturer=TDK, Supplier Part Number 1=445-6000-1-ND, TempCo=X5R, Tolerance_%=20%, Value1=Unknown, Value2=25V, ValueDisplayed=22uF
C17: library part CMP-0006327-2, "CAP, CERM, 0.015 uF, 50 V, +/- 10%, X7R, AEC-Q200 Grade 1, 0402", Cap_Case=0402, Manufacturer=TDK, Supplier Part Number 1=445-6894-1-ND, TempCo=X7R, Tolerance_%=10%, Value1="0.2162 ohm", Value2=50V, ValueDisplayed=0.015uF
C18 C26 C29 C32: library part CMP-0008016-2, "CAP, CERM, 10 uF, 6.3 V, +/- 10%, X7R, AEC-Q200 Grade 1, 0805", Cap_Case=0805, Manufacturer=MuRata, Supplier Part Number 1=490-5319-1-ND, TempCo=X7R, Tolerance_%=10%, Value1=Unknown, Value2=6.3V, ValueDisplayed=10uF
C20 C22 C25 C28 C31 C34: library part CMP-0009642-3, "CAP, CERM, 0.01 uF, 10 V, +/- 10%, X7R, AEC-Q200 Grade 1, 0201", Cap_Case=0201_033, Manufacturer=TDK, Supplier Part Number 1=445-12059-1-ND, TempCo=X7R, Tolerance_%=10%, Value1="0.280214 ohm", Value2=10V, ValueDisplayed=0.01uF
C23: library part CMP-0006358-2, "CAP, CERM, 0.022 uF, 50 V, +/- 10%, C0G/NP0, 0402", Cap_Case=0402, Manufacturer=MuRata, Supplier Part Number 1=490-4763-1-ND, TempCo=C0G/NP0, Tolerance_%=10%, Value1=Unknown, Value2=50V, ValueDisplayed=0.022uF
FID1 FID2 FID3: library part CMP-0077181-1, "Fiducial mark.  There is nothing to buy or mount.", Manufacturer=N/A
J1: library part CMP-0055621-1, "Receptacle, 0.5mm, 30x2, Gold, SMT", Color=Black, Current_A=1.5A, Manufacturer=Samtec
J2: library part CMP-0075127-1, "Connector, HF, 50 Ohm, TH", Color=Waterblue, Manufacturer=Rosenberger
L1: library part CMP-0081093-1, "Inductor, Shielded, Metal Composite, 1.5 µH, 2.3 A, 0.11 ohm, AEC-Q200 Grade 0, SMD", Manufacturer=TDK, Supplier Part Number 1=445-174575-1-ND, Value1="0.11 ohm", Value2=2.3A, ValueDisplayed=1.5µH
L2 L3: library part CMP-0081092-1, "Inductor, Shielded, Metal Composite, 1 µH, 3.1 A, 0.06 ohm, AEC-Q200 Grade 0, SMD", Manufacturer=TDK, Supplier Part Number 1=445-174574-1-ND, Value1="0.06 ohm", Value2=3.1A, ValueDisplayed=1µH
L4 L9 L10 L11 L12 L13: library part CMP-0003310-1, "Ferrite Bead, 1000 ohm @ 100 MHz, 0.3 A, 0402", Manufacturer=MuRata, Supplier Part Number 1=490-1007-1-ND, Value1="0.65 ohm", Value2=0.3A, ValueDisplayed="1000 ohm"
L5: library part CMP-0058702-1, "Inductor, Wirewound, Ferrite, 10 uH, 0.81 A, 0.288 ohm, AEC-Q200 Grade 1, SMD", Manufacturer=MuRata, Supplier Part Number 1=81-LQH3NPZ100MJRL, Value1="0.288 ohm", Value2=0.81A, ValueDisplayed=10uH
L6 L7 L8: library part CMP-0003349-2, "Ferrite Bead, 1500 ohm @ 100 MHz, 0.5 A, 0603", Manufacturer=MuRata, Supplier Part Number 1=490-5216-1-ND, Value1="0.5 ohm", Value2=0.5A, ValueDisplayed="1500 ohm"
Logo2: library part CMP-0074838-1, "Texas Instrument Corporate Signature"
R1 R2 R3 R4 R5 R6 R8 R16 R17: library part CMP-0026992-3, "RES, 0, 5%, 0.1 W, AEC-Q200 Grade 0, 0402", Manufacturer=Panasonic, Power_W=100mW, Supplier Part Number 1=P0.0JCT-ND, TempCo="600 ppm/C", Tolerance_%=5%, Value2=0.1W, Value_Code=0000, ValueDisplayed=0
R7 R11 R12: library part CMP-0026938-5, "RES, 4.7 k, 5%, 0.063 W, AEC-Q200 Grade 0, 0402", Manufacturer=Vishay-Dale, Power_W=63mW, Supplier Part Number 1=541-4.7KJCT-ND, TempCo="200 ppm/C", Tolerance_%=5%, Value2=0.063W, Value_Code=4k70, ValueDisplayed=4.7k
R9: library part CMP-0026405-2, "RES, 4.02 k, 1%, 0.063 W, AEC-Q200 Grade 0, 0402", Manufacturer=Vishay-Dale, Power_W=63mW, Supplier Part Number 1=541-4.02KLCT-ND, TempCo="100 ppm/C", Tolerance_%=1%, Value2=0.063W, Value_Code=4k02, ValueDisplayed=4.02k
R10: library part CMP-0027279-3, "RES, 49.9, 1%, 0.05 W, 0201", Manufacturer=Vishay-Dale, Power_W=50mW, Supplier Part Number 1=541-49.9AABCT-ND, TempCo="100 ppm/C", Tolerance_%=1%, Value2=0.05W, Value_Code=49R9, ValueDisplayed=49.9
R13: library part CMP-0027015-3, "RES, 22, 5%, 0.05 W, AEC-Q200 Grade 1, 0201", Manufacturer=Panasonic, Power_W=50mW, Supplier Part Number 1=ERJ-1GNJ220C-ND, TempCo="200 ppm/C", Tolerance_%=5%, Value2=0.05W, Value_Code=22R0, ValueDisplayed=22
R14 R15: library part CMP-0026366-2, "RES, 402, 1%, 0.063 W, AEC-Q200 Grade 0, 0402", Manufacturer=Vishay-Dale, Power_W=63mW, Supplier Part Number 1=541-402LCT-ND, TempCo="100 ppm/C", Tolerance_%=1%, Value2=0.063W, Value_Code=402R, ValueDisplayed=402
TP1 TP2 TP3 TP4 TP5 TP6 TP7 TP8 TP9 TP10 TP11 TP12 TP13 TP14: library part CMP-0003719-1, "Testpoint", Manufacturer="Texas Instruments"
TP15: library part CMP-0055138-1, "Test Point, Miniature, Black, TH", Color=Black, Manufacturer=Keystone, Supplier Part Number 1=36-5001-ND
U1: library part CMP-0080054-3, "Automotive Camera PMIC, RGE0024K (VQFN-24)", Alternate Manufacturer="Texas Instruments"
U2: library part CMP-0084098-1, "2MP MIPI CSI-2 FPD-Link III Serializer for 2MP/60fps Cameras and RADAR, RHB0032P (VQFN-32)", Alternate Manufacturer="Texas Instruments", Alternate PartNumber=DS90UB953TRHBTQ1, Operating Temperature Range="-40 to 105 C", Rating=Automotive
ZZ1: library part CMP-0077236-1
ZZ2: library part CMP-0077237-1
ZZ3: library part CMP-0077238-1

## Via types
v1: diameter 18, hole 8, TOP to BOTTOM, 147 vias
v2: diameter 22, hole 12, TOP to BOTTOM, 36 vias
v3: diameter 19.68, hole 7.87, TOP to BOTTOM, 17 vias

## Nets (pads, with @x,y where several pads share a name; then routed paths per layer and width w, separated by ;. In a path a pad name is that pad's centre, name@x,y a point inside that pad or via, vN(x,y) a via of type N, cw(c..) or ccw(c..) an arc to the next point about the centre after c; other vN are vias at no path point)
953_CLKOUT: J1.13 R13.1 | length 1063.6
  TOP w6: R13.1@920.8,566.29 v1(920.8,590.8)
  INNER1 w6: v1(327.1,885.8) 339.8,873.1 339.8,655.8 312.3,628.3 312.3,565.8 334.8,543.3 462.3,543.3 544,625 886.6,625 v1(920.8,590.8)
  BOTTOM w9: v1(327.1,885.8) J1.13@327.1,922.4
953_GPIO0: J1.53 U2.17 | length 597
  TOP w6: U2.17@868.23,471.9 896.2,471.9 v1(907.3,460.8)
  INNER2 w6: v1(720.8,893.3) 720.8,847.3 869.8,698.3 869.8,595.8 852.3,578.3 852.3,515.8 v1(907.3,460.8)
  BOTTOM w9: v1(720.8,893.3) J1.53@720.8,922.4
953_GPIO1: J1.55 U2.18 | length 613.3
  TOP w6: U2.18@868.23,491.59 v1(907.3,491.59)
  INNER2 w6: v1(740.5,952.3) 740.5,857.6 892.3,705.8 892.3,585.8 874.8,568.3 874.8,524.09 v1(907.3,491.59)
  BOTTOM w9: J1.55@740.5,922.4 v1(740.5,952.3)
953_GPIO2: R5.1 U2.27 | length 565.7
  TOP w6: U2.27@799.33,639.23 v1(799.33,680.8)
  INNER1 w6: v1(409.8,633.3) 441.5,665 783.53,665 v1(799.33,680.8)
  BOTTOM w6: R5.1@301.68,649.8 325.8,649.8 342.3,633.3 v1(409.8,633.3)
953_GPIO3: R8.1 R17.1 U2.28 | length 132.7
  TOP w6: U2.28@779.64,639.23 779.64,696.64 787.3,704.3 787.3,725.22 R17.1@830.8,725.22
CSI2_CK_N: J1.25 U2.6 | length 585.1
  TOP w5.1: v1@422.3,807.8 424.8,805.3 424.8,789.89 419.2,784.29 419.2,778.39 424.8,772.79 424.8,662.08 573.26,513.62 669.02,513.62 U2.6@671.37,511.27
  BOTTOM w5.1: v1@422.3,807.8 423.3,807.8 442.8,827.3 442.8,920 J1.25@445.2,922.4
  other v1: 422,807
CSI2_CK_P: J1.23 U2.5 | length 585.1
  TOP w5.1: v1@422.3,830.8 422.71,830.8 439.8,813.71 439.8,668.3 579.48,528.62 669.03,528.62 U2.5@671.37,530.96
  BOTTOM w5.1: v1@422.3,830.8 427.8,836.3 427.8,849.39 424.55,852.64 419.55,852.64 416.3,855.89 416.3,860.49 419.55,863.74 424.55,863.74 427.8,866.99 427.8,871.59 424.55,874.84 419.95,874.84 416.7,878.09 416.7,882.69 419.95,885.94 424.35,885.94 427.8,889.39 427.8,920.1 J1.23@425.5,922.4
  other v1: 422,832
CSI2_D0_N: J1.31 U2.4 | length 583.2
  TOP w5.1: v1@478.9,775.8 480.8,773.9 480.8,760.72 475.2,755.12 475.2,748.72 480.8,743.12 480.8,733.01 465.8,718.01 465.8,682.18 482.18,665.8 496.07,665.8 501.3,660.57 501.3,643.29 518.79,625.8 545.8,625.8 552.3,619.3 552.3,592.29 591.6,552.99 669.02,552.99 U2.4@671.37,550.64
  BOTTOM w5.1: v1@478.9,775.8 482.9,779.8 510.58,779.8 524.46,793.68 524.46,816.14 501.95,838.65 501.95,920.05 J1.31@504.3,922.4
  other v1: 479,775
CSI2_D0_P: J1.29 U2.3 | length 583.2
  TOP w5.1: v1@478.9,798.8 479.31,798.8 495.8,782.31 495.8,726.79 480.8,711.79 480.8,688.4 488.4,680.8 502.29,680.8 516.3,666.79 516.3,649.51 525.01,640.8 552.02,640.8 567.3,625.52 567.3,598.51 597.82,567.99 669.03,567.99 U2.3@671.37,570.33
  BOTTOM w5.1: v1@478.9,798.8 482.9,794.8 504.36,794.8 509.46,799.9 509.46,809.92 486.95,832.43 486.95,853.25 483.58,856.62 480.15,856.62 476.9,859.87 476.9,864.47 480.15,867.72 483.7,867.72 486.95,870.97 486.95,875.57 483.7,878.82 480.15,878.82 476.9,882.07 476.9,886.67 480.15,889.92 483.62,889.92 486.95,893.25 486.95,920.05 J1.29@484.6,922.4
  other v1: 479,800
CSI2_D1_N: J1.35 U2.2 | length 584.6
  TOP w5.1: v1@546.8,853.3 542.8,849.3 525.68,849.3 511.8,835.42 511.8,808.58 522.3,798.08 522.3,699.07 551.68,669.69 632.19,669.69 637.8,664.08 637.8,651.5 632.2,645.9 610.67,645.9 595.8,631.03 595.8,607.6 611.05,592.35 669.03,592.35 U2.2@671.37,590.01
  BOTTOM w5.1: J1.35@543.6,922.4 541.3,920.1 541.3,897.32 544.55,894.07 556.75,894.07 560,890.82 560,886.22 556.75,882.97 544.55,882.97 541.3,879.72 541.3,858.8 v1@546.8,853.3
  other v1: 547,854
CSI2_D1_P: J1.33 U2.1 | length 584.6
  TOP w5.1: v1@546.8,830.3 542.8,834.3 531.9,834.3 526.8,829.2 526.8,814.8 537.3,804.3 537.3,768.33 540.55,765.08 545.55,765.08 548.8,761.83 548.8,757.23 545.55,753.98 540.55,753.98 537.3,750.73 537.3,746.13 540.55,742.88 545.55,742.88 548.8,739.63 548.8,735.03 545.55,731.78 540.55,731.78 537.3,728.53 537.3,705.29 557.9,684.69 568.24,684.69 571.49,687.94 571.49,694.75 574.74,698 579.34,698 582.59,694.75 582.59,688.02 585.92,684.69 638.41,684.69 652.8,670.3 652.8,645.28 638.42,630.9 616.89,630.9 610.8,624.81 610.8,613.82 617.27,607.35 669.02,607.35 U2.1@671.37,609.7
  BOTTOM w5.1: J1.33@524,922.4 526.3,920.1 526.3,849.8 545.8,830.3 v1@546.8,830.3
  other v1: 547,829
CSI2_D2_N: J1.41 U2.32 | length 580.6
  TOP w5.1: v1@579.8,775.8 587.3,768.3 587.3,756.92 584.05,753.67 572.05,753.67 568.8,750.42 568.8,745.82 572.05,742.57 584.05,742.57 587.3,739.32 587.3,726.3 605.3,708.3 671.08,708.3 703.24,676.14 U2.32@703.24,641.57
  BOTTOM w5.1: v1@579.8,775.8 583.8,779.8 682.52,779.8 696.41,793.69 696.41,819.41 682.52,833.3 624.8,833.3 600.35,857.75 600.35,920.05 J1.41@602.7,922.4
  other v1: 580,775
CSI2_D2_P: J1.39 U2.31 | length 580.7
  TOP w5.1: v1@579.8,798.8 580.21,798.8 602.3,776.71 602.3,732.52 611.52,723.3 677.3,723.3 718.24,682.36 U2.31@718.24,641.58
  BOTTOM w5.1: v1@579.8,798.8 583.8,794.8 595.57,794.8 598.82,798.05 598.82,800.05 602.07,803.3 606.67,803.3 609.92,800.05 609.92,798.05 613.17,794.8 676.3,794.8 681.41,799.91 681.41,813.19 676.3,818.3 618.58,818.3 585.35,851.53 585.35,860.36 582.1,863.61 577.05,863.61 573.8,866.86 573.8,871.46 577.05,874.71 582.1,874.71 585.35,877.96 585.35,920.05 J1.39@583,922.4
  other v1: 580,800
CSI2_D3_N: J1.45 U2.30 | length 580.2
  TOP w5.1: U2.30@742.61,641.57 742.61,699.77 724.8,717.58 724.8,784.52 735.8,795.52 735.8,811.58 724.8,822.58 724.8,856.92 738.68,870.8 784.3,870.8 v1(788.3,874.8)
  BOTTOM w5.1: J1.45@642.1,922.4 639.75,920.05 639.75,875.9 644.85,870.8 654.07,870.8 657.32,874.05 657.32,878.05 660.57,881.3 665.17,881.3 668.42,878.05 668.42,874.05 671.67,870.8 692.25,870.8 695.5,874.05 695.5,877.05 698.75,880.3 703.35,880.3 706.6,877.05 706.6,874.05 709.85,870.8 718.5,870.8 732.38,856.92 732.38,838.28 736.86,833.8 749.7,833.8 754.18,838.28 754.18,857.54 767.44,870.8 784.3,870.8 v1(788.3,874.8)
CSI2_D3_P: J1.43 U2.29 | length 580.2
  TOP w5.1: U2.29@757.61,641.58 757.61,705.99 739.8,723.8 739.8,778.3 750.8,789.3 750.8,817.8 739.8,828.8 739.8,850.7 744.9,855.8 754.65,855.8 757.9,852.55 757.9,842.85 761.15,839.6 765.75,839.6 769,842.85 769,852.55 772.25,855.8 784.3,855.8 v1(788.3,851.8)
  BOTTOM w5.1: J1.43@622.4,922.4 624.75,920.05 624.75,869.68 638.63,855.8 712.28,855.8 717.38,850.7 717.38,832.06 730.64,818.8 755.92,818.8 769.18,832.06 769.18,851.32 773.66,855.8 784.3,855.8 v1(788.3,851.8)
